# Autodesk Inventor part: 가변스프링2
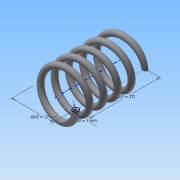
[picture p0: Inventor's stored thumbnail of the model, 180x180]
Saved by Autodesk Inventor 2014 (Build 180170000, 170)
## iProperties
Created: 2015-09
Part Number: 가변스프링2
Material: Generic
Document SubType Name: Modeling
Designer: study
Density: 1 g/cm^3
Appearance: Default
Author: study
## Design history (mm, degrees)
sketch "스케치1"
  geometry: L1 (0, 0)-(11, 0); L2 (11, 0)-(11, 37); L3 (11, 37)-(0, 37); L4 (0, 37)-(0, 0); C1 r 1.5 at (11, 0)
  constraints: 8 end point, 2 parallel, 1 centre point, 1 coincident, 1 horizontal, 1 perpendicular
  dimensions: "d0" = 3 diameter of C1; "d2" = 22 diameter of L2 L4; "d3" = 37 distance of L1.end L2.end (derived)
feature "코일1" sketch "스케치1" pitch "d4" = 10; turns "d6" = 5; dims "d5" = 37 (= d3), "d7" = 0, angle "d8" = 90 deg, angle "d9" = 90 deg, "d10" = 0, "d11" = 0
node "작업 평면1"
sketch "스케치2"
  geometry: L1 (-12.5, 0)-(-9.5, 0) reference; 1 further point
  constraints: 1 horizontal alignment
extrude "돌출1" cut sketch "스케치2" stored distance "d13" = 10; taper "d14" = 0 deg
node "작업 평면2"
sketch "스케치3"
  geometry: L1 (-9.5, 0)-(-12.5, 0) reference; 1 further point
  constraints: 1 horizontal alignment
extrude "돌출2" cut sketch "스케치3" stored distance "d16" = 10; taper "d17" = 0 deg
node "솔리드1"
node "절단 모서리 투영1"
node "절단 모서리 투영2"
other parameters: "d12" = 0, "d15" = 37 (= d3)
